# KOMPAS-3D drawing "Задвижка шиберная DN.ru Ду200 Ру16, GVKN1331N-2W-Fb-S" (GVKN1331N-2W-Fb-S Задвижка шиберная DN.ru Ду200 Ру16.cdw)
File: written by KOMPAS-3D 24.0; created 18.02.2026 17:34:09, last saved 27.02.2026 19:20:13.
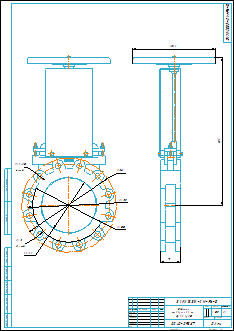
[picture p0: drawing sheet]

Document properties: art: D040-09387; Автор: R2D2; Форматы листов документа: A2; Полное имя файла: GVKN1331N-2W-Fb-S Задвижка шиберная DN.ru Ду200 Ру16.m3d; Масса: 26.5; Наименование: Задвижка шиберная DN.ru Ду200 Ру16; Количество листов документа: 1; Примечание: D040-09387

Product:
- Part/product: Задвижка шиберная DN.ru Ду200 Ру16  | designation GVKN1331N-2W-Fb-S
    Масса: 26.5
    Раздел спецификации: Прочие изделия
    Форматы листов документа: A2
    Примечание: D040-09387
    additional columns: D040-09387

Views: Вид 1, Спереди, Проекционный вид 2
Referenced files in E:\Работа\Зайцев\GVKN1331N-2W-Fb-S Задвижка шиберная DN.ru Ду50-300 Ру10\DN200 PN16\: GVKN1331N-2W-Fb-S Задвижка шиберная DN.ru Ду200 Ру16.m3d
Referenced files in E:\Работа\Зайцев\Для компаса\: чертеж DN.ru.cdt
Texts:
  GVKN1331N-2W-Fb-S
  чертеж DN.ru.cdt
  Задвижка
  шиберная DN.ru
  Ду200 Ру16
  prop
  Задвижка шиберная DN.ru Ду200 Ру16
  GVKN1331N-2W-Fb-S Задвижка шиберная DN.ru Ду200 Ру16
Dimensions and other numbers on the sheet: 0; 3; 2; 4; 340; 295; 266; 23; 8 отв.; 200; 20; 4 отв.; 70; 531; 300; 1:2; 1; 26,5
